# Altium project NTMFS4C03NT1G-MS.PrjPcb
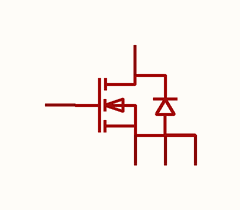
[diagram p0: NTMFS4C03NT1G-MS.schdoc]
1 sheet, 1 parts. Net scope: global (net labels, ports and power ports of the same name join across sheets).

## Sheet NTMFS4C03NT1G-MS.schdoc
size 127 x 101 mm

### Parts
Q?  ntmfs4c03nt1g-ms  [TDSON-8_L5.9-W5.2-P1.27-BL]  (value not drawn)

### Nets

Not connected (* = marked no-connect by the designer): Q? 1(S) 2(S) 3(S) 4(G) 5(D)

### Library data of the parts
Q? = ntmfs4c03nt1g-ms: 数量:1个N沟道;漏源电压(Vdss):30V;连续漏极电流(Id):150A;导通电阻(RDS(on)):3.2mΩ@4.5V,15A;耗散功率(Pd):187W;阈值电压(Vgs(th)):2.5V@250uA;; Manufacturer: MSKSEMI(美森科); AddInBom: yes; ModelId: ff3d8edf19694f3eb1c5df98919f3bc8; ModelTransform: 216.9287,242.5192,0,0,0,0,0,43.307,0; Number: 1个N沟道; Drain to Source Voltage: 30V; Current - Continuous Drain(Id): 150A; Pd - Power Dissipation: 187W; Gate Charge(Qg): 56.9nC@10V; Input Capacitance(Ciss): 4.345nF; Reverse Transfer Capacitance (Crss@Vds): 225pF; Type: N沟道; Output Capacitance(Coss): 340pF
